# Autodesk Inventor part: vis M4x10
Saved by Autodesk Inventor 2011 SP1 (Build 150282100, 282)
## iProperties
Created: 2010-12
Part Number: vis M4x10
Document SubType Name: Modeling
Designer: eric
Density: 1 g/cm^3
Author: eric
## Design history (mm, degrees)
feature "Base1"
node "Solide1"
node "Corps solides"
node "Corps surfaciques"
